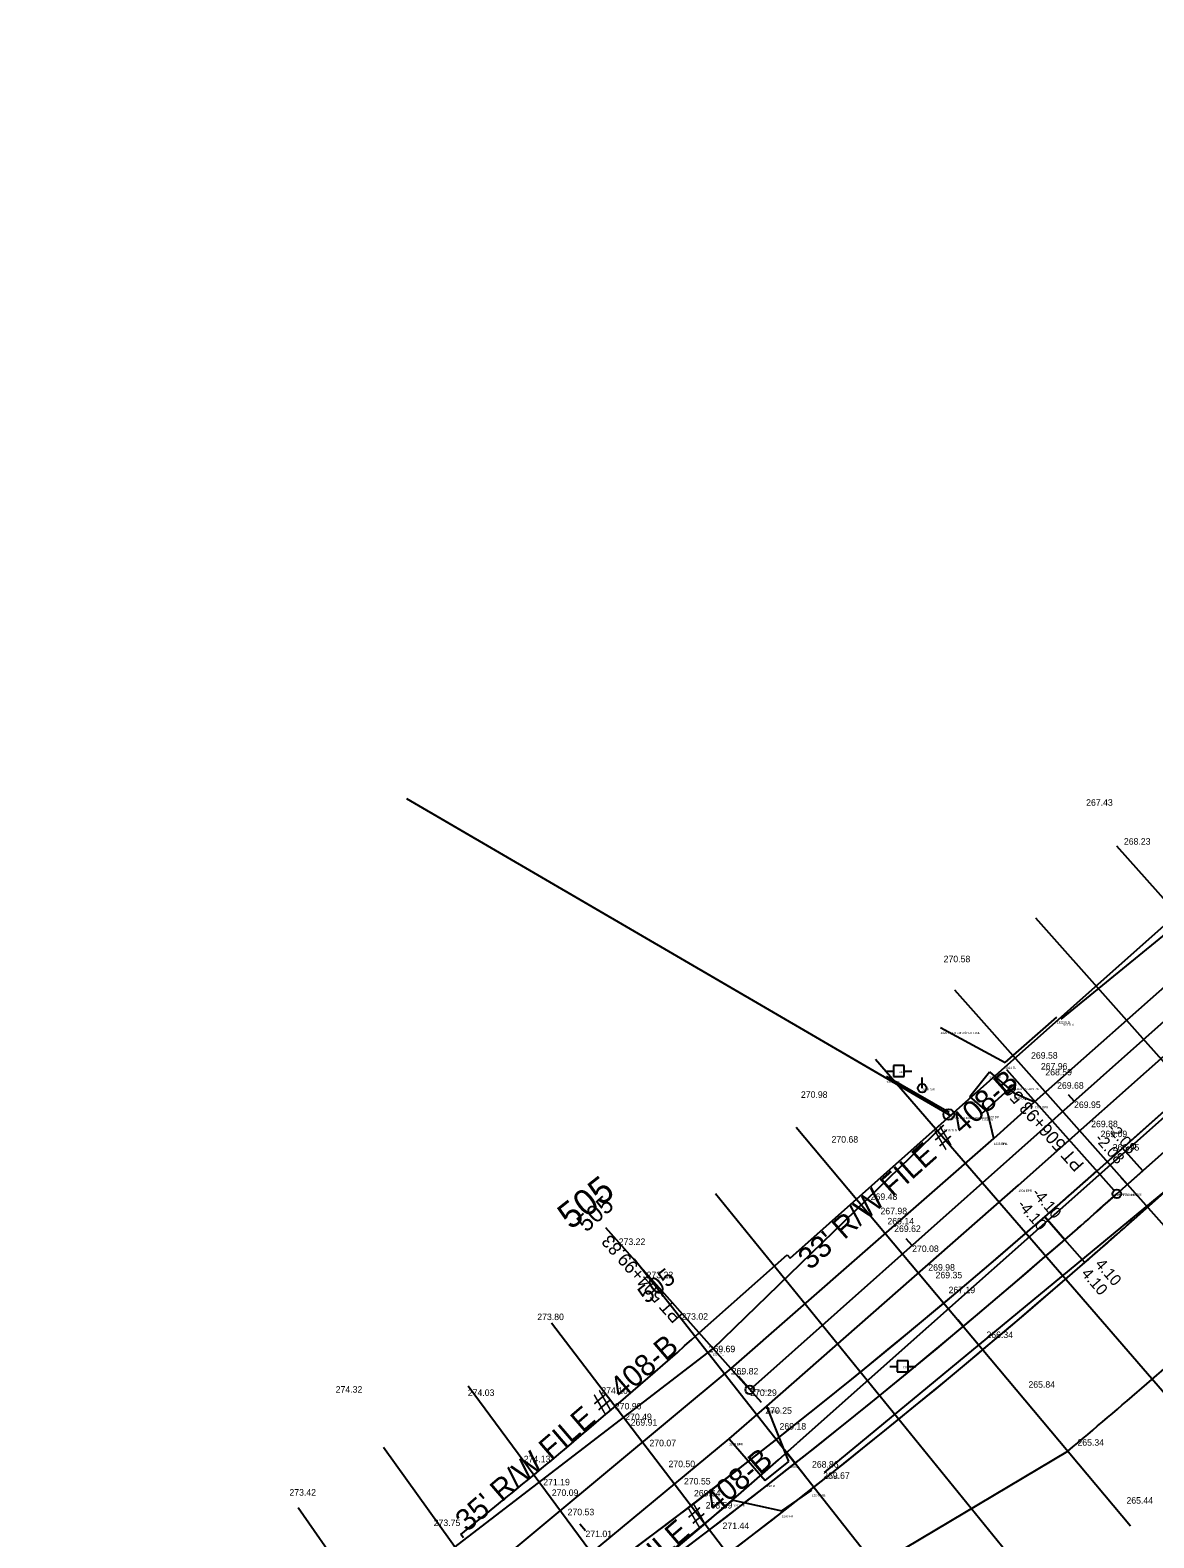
# Model space of a CAD drawing. Extents: x 49683 to 58852, y 49525 to 54803.
# Drawn here: x 52213 to 52731, y 50615 to 51310 of the extents above; entities that cross this region are included whole.
import ezdxf

# ---------------------------------------------------------------- set-up
doc = ezdxf.new("R2010")
doc.units = 0
for name, color, linetype in [('Level 1', 7, 'Continuous'), ('Level 11', 7, 'Continuous'), ('Level 12', 7, 'Continuous'), ('Level 13', 7, 'Continuous'), ('Level 19', 7, 'Continuous'), ('Level 20', 7, 'Continuous'), ('Level 21', 7, 'Continuous'), ('Level 25', 7, 'Continuous'), ('Level 29', 7, 'Continuous'), ('Level 3', 7, 'Continuous'), ('Level 32', 7, 'Continuous'), ('Level 33', 7, 'Continuous'), ('Level 50', 7, 'Continuous'), ('Level 51', 7, 'Continuous'), ('Level 53', 7, 'Continuous'), ('Level 56', 7, 'Continuous'), ('Level 58', 7, 'Continuous'), ('Level 59', 7, 'Continuous'), ('Level 6', 7, 'Continuous'), ('Level 61', 7, 'Continuous'), ('Level 62', 7, 'Continuous'), ('Level 63', 7, 'Continuous'), ('Level 8', 7, 'Continuous'), ('Level 9', 7, 'Continuous')]:
    doc.layers.add(name, color=color, linetype=linetype)

# ---------------------------------------------------------------- blocks, each defined once
blk = doc.blocks.new('PP')
at = {"layer": 'Level 9'}
for p, q in [((2.53, 2.45), (-2.47, 2.45)), ((-2.47, 2.45), (-2.47, -2.55)), ((2.53, -2.55), (2.53, 2.45)), ((-5.91, -0.11), (-2.44, -0.11)), ((-2.47, -2.55), (2.53, -2.55)), ((2.45, -0.11), (6.09, -0.11))]:
    blk.add_line(p, q, dxfattribs=at)
blk = doc.blocks.new('GW')
at = {"layer": 'Level 9'}
blk.add_line((0, 0), (0, 5), dxfattribs=at)
blk.add_circle((0, 0), 2, dxfattribs=at)
blk = doc.blocks.new('IP')
at = {"layer": 'Level 12'}
for radius in [2.5, 0.25]:
    blk.add_circle((0, 0), radius, dxfattribs=at)

msp = doc.modelspace()

# ---------------------------------------------------------------- linework, layer by layer
at = {"layer": 'Level 1'}
for p, q in [((52544.81, 50683.3), (55534.58, 53340.86)), ((52694.42, 50816.29), (52691.76, 50819.28)), ((52543.48, 50684.8), (52478.41, 50758)), ((52619.68, 50749.85), (52617.02, 50752.84)), ((52544.94, 50683.42), (52539.62, 50689.4)), ((52550.25, 50677.44), (52544.94, 50683.42)), ((52469.06, 50618.29), (52466.5, 50621.38))]:
    msp.add_line(p, q, dxfattribs=at)
msp.add_circle((52544.81, 50683.3), 2, dxfattribs=at)
at = {"layer": 'Level 11'}
for p, q in [((52688.43, 50854.08), (52940.3, 51059.99)), ((52579.25, 50645.17), (52882.73, 50895.61)), ((52527.71, 50702.05), (52634.35, 50805.36)), ((52331.92, 50551.79), (52527.71, 50702.05))]:
    msp.add_line(p, q, dxfattribs=at)
at = {"layer": 'Level 12'}
for p, q in [((52386.57, 50955.87), (52637.37, 50809.73)), ((52412.79, 50615.02), (52411.54, 50616.58))]:
    msp.add_line(p, q, dxfattribs=at)
at = {"layer": 'Level 13'}
for p, q in [((52637.37, 50809.73), (53363.85, 51455.49)), ((53407.7, 51406.16), (52566.74, 50658.64)), ((52563.41, 50743.99), (52637.37, 50809.73)), ((52521.55, 50709.46), (52562.08, 50745.49)), ((52562.08, 50745.49), (52563.41, 50743.99))]:
    msp.add_line(p, q, dxfattribs=at)
for radius, start, end in [(2829.79, 308.71775, 311.63328), (2897.79, 282.71776, 311.63339)]:
    msp.add_arc((50641.55, 52824.48), radius, start, end, dxfattribs=at)
at = {"layer": 'Level 19'}
for p, q in [((52714.15, 50773.62), (54181.77, 52078.16)), ((52712.83, 50775.12), (52663.38, 50830.74)), ((52718.97, 50777.9), (52716.31, 50780.89)), ((52643.35, 50712.47), (52640.78, 50715.54)), ((52565.77, 50649.38), (52560.82, 50655.66)), ((52565.77, 50649.38), (52570.72, 50643.1))]:
    msp.add_line(p, q, dxfattribs=at)
msp.add_circle((52714.15, 50773.62), 2, dxfattribs=at)
msp.add_arc((50539, 53220.69), 3274.06, 284.51284, 311.63337, dxfattribs=at)
at = {"layer": 'Level 20'}
for p, q in [((52704.85, 50784.08), (53476.26, 51469.77)), ((52723.45, 50763.15), (53495.78, 51449.66))]:
    msp.add_line(p, q, dxfattribs=at)
for radius in [3260.06, 3288.06]:
    msp.add_arc((50539, 53220.69), radius, 284.51284, 311.63318, dxfattribs=at)
at = {"layer": 'Level 29'}
for p, q in [((52714.15, 50773.62), (54181.77, 52078.16)), ((52712.83, 50775.12), (52663.38, 50830.74)), ((52718.97, 50777.9), (52716.31, 50780.89)), ((52643.35, 50712.47), (52640.78, 50715.54)), ((52565.77, 50649.38), (52560.82, 50655.66))]:
    msp.add_line(p, q, dxfattribs=at)
msp.add_circle((52714.15, 50773.62), 2, dxfattribs=at)
msp.add_arc((50539, 53220.69), 3274.06, 284.51246, 311.63337, dxfattribs=at)
at = {"layer": 'Level 3'}
for p, q in [((52676.2, 50815.96), (52945.93, 51055.32)), ((52668.7, 50777.53), (52961.4, 51037.52)), ((52657.35, 50799.14), (52676.2, 50815.96)), ((52536.19, 50693.05), (52657.35, 50799.14)), ((52552.71, 50675.77), (52668.7, 50777.53)), ((52383.07, 50565.65), (52536.19, 50693.05)), ((52535.34, 50660.73), (52552.71, 50675.77)), ((52398.28, 50547.35), (52535.34, 50660.73))]:
    msp.add_line(p, q, dxfattribs=at)
at = {"layer": 'Level 33'}
msp.add_line((52602.91, 50602.26), (52691.55, 50655.02), dxfattribs=at)
msp.add_arc((50539, 53220.69), 3349.06, 309.99611, 311.63318, dxfattribs=at)
at = {"layer": 'Level 50'}
for p, q in [((52713.99, 50934.03), (52873.43, 50754.65)), ((52676.62, 50900.81), (52836.06, 50721.43)), ((52639.25, 50867.59), (52798.69, 50688.21)), ((52602.88, 50835.64), (52759.93, 50654.16)), ((52566.22, 50804.4), (52720.48, 50620.54)), ((52529.09, 50773.73), (52680.52, 50587.53)), ((52491.49, 50743.62), (52640.06, 50555.14)), ((52453.43, 50714.1), (52599.11, 50523.36)), ((52414.93, 50685.15), (52557.67, 50492.22)), ((52375.99, 50656.8), (52515.77, 50461.71)), ((52336.62, 50629.05), (52473.41, 50431.84))]:
    msp.add_line(p, q, dxfattribs=at)
at = {"layer": 'Level 6'}
msp.add_line((52667.22, 50824.46), (52651.63, 50810.3), dxfattribs=at)
at = {"layer": 'Level 63'}
for p, q in [((52716.81, 50794.72), (53451.1, 51447.41)), ((53460.4, 51436.95), (52726.11, 50784.25)), ((52714.15, 50773.62), (52800.86, 50850.69)), ((52810.16, 50840.23), (52723.45, 50763.15)), ((52716.81, 50794.72), (52704.85, 50784.08)), ((52726.11, 50784.25), (52716.81, 50794.72)), ((52726.11, 50784.25), (52716.81, 50794.72)), ((52714.15, 50773.62), (52726.11, 50784.25)), ((52690.14, 50752.48), (52680.94, 50763.04)), ((52680.94, 50763.04), (52690.14, 50752.48)), ((52699.33, 50741.93), (52690.14, 50752.48)), ((52699.33, 50741.93), (52690.14, 50752.48))]:
    msp.add_line(p, q, dxfattribs=at)
for radius, start, end in [(3260.06, 311.07341, 311.63319), (3274.06, 311.07341, 311.63337), (3274.06, 311.07341, 311.63337), (3260.06, 284.51284, 311.07341), (3288.06, 311.07341, 311.63319), (3274.06, 284.51284, 311.07341), (3274.06, 284.51284, 311.07341), (3288.06, 284.51284, 311.07341)]:
    msp.add_arc((50539, 53220.69), radius, start, end, dxfattribs=at)
at = {"layer": 'Level 8'}
for p, q in [((52662.65, 50834.17), (52686.48, 50855.13)), ((52632.81, 50850.29), (52662.65, 50834.17)), ((52636.74, 50811.07), (52607.92, 50827.67)), ((52646.27, 50818.43), (52655.35, 50829.84)), ((52655.35, 50829.84), (52666.62, 50820.18)), ((52654.44, 50811.48), (52646.27, 50818.43)), ((52666.62, 50820.18), (52676.2, 50815.96)), ((52657.35, 50799.14), (52654.44, 50811.48)), ((52562.88, 50650.26), (52552.71, 50675.77)), ((52535.34, 50660.73), (52551.99, 50641.44)), ((52551.99, 50641.44), (52562.88, 50650.26)), ((52559.58, 50627.44), (52573.52, 50637.05)), ((52412.59, 50530.13), (52537.26, 50632.33)), ((52537.26, 50632.33), (52559.58, 50627.44))]:
    msp.add_line(p, q, dxfattribs=at)

# ---------------------------------------------------------------- block references
at = {"layer": 'Level 12'}
msp.add_blockref('IP', (52636.62, 50810.17), dxfattribs=at)
at = {"layer": 'Level 9'}
for name, p in [('PP', (52613.57, 50830.29)), ('GW', (52624.36, 50822.3)), ('PP', (52615.32, 50694.1))]:
    msp.add_blockref(name, p, dxfattribs=at)

# ---------------------------------------------------------------- texts
at = {"layer": 'Level 1'}
msp.add_text('PT 504+99.83', height=6, rotation=131.63333, dxfattribs=at).set_placement((52514.08, 50717.4))
at = {"layer": 'Level 19'}
for s, height, rotation, p in [('PT 506+93.56', 6, 131.63336, (52699.37, 50787.24)), ('505', 8, 38.24612, (52497.19, 50722.66))]:
    msp.add_text(s, height=height, rotation=rotation, dxfattribs=at).set_placement(p)
at = {"layer": 'Level 21'}
for height, rotation, p in [(12, 38.24612, (52462.28, 50756.75)), (8, 41.63333, (52469.43, 50755.59))]:
    msp.add_text('505', height=height, rotation=rotation, dxfattribs=at).set_placement(p)
at = {"layer": 'Level 25'}
for s, rotation, p in [("33' R/W FILE # 408-B", 41.63333, (52572.62, 50738.12)), ("35' R/W FILE # 408-B", 40.74622, (52414.47, 50617.41)), ("33' R/W FILE # 408-B", 40.72213, (52457.9, 50565.13))]:
    msp.add_text(s, height=10, rotation=rotation, dxfattribs=at).set_placement(p)
at = {"layer": 'Level 29'}
msp.add_text('PT 506+93.56', height=6, rotation=131.63336, dxfattribs=at).set_placement((52699.37, 50787.24))
at = {"layer": 'Level 32'}
for s, p in [('267.43', (52699.98, 50952.52)), ('268.23', (52717.38, 50934.57)), ('270.58', (52634.26, 50880.38)), ('269.58', (52674.56, 50835.92)), ('267.96', (52679.1, 50830.92)), ('268.59', (52681.16, 50828.21)), ('269.68', (52686.58, 50822.08)), ('270.98', (52568.44, 50817.86)), ('269.95', (52694.4, 50813.18)), ('269.88', (52702.29, 50804.34)), ('269.09', (52706.63, 50799.75)), ('270.68', (52582.55, 50797.22)), ('266.95', (52712.21, 50793.54)), ('269.48', (52600.61, 50770.8)), ('267.98', (52605.13, 50764.2)), ('269.14', (52608.33, 50759.52)), ('269.62', (52611.44, 50756.05)), ('273.22', (52484.4, 50750.05)), ('270.08', (52619.73, 50746.79)), ('269.98', (52627.18, 50738.19)), ('273.22', (52497.26, 50734.72)), ('269.35', (52630.53, 50734.64)), ('267.19', (52636.52, 50727.8)), ('273.80', (52446.85, 50715.4)), ('273.02', (52513.33, 50715.57)), ('266.34', (52653.99, 50707.13)), ('269.69', (52525.85, 50700.63)), ('269.69', (52525.9, 50700.58)), ('269.82', (52536.52, 50690.34)), ('274.32', (52353.88, 50681.95)), ('274.10', (52476.36, 50681.43)), ('265.84', (52673.36, 50684.23)), ('274.03', (52414.8, 50680.43)), ('270.29', (52545.04, 50680.43)), ('270.90', (52482.63, 50674.21)), ('270.49', (52487.39, 50669.32)), ('270.25', (52552.01, 50672.2)), ('269.91', (52489.93, 50666.75)), ('269.18', (52558.57, 50664.94)), ('270.07', (52498.57, 50657.24)), ('265.34', (52695.96, 50657.5)), ('274.13', (52440.6, 50649.87)), ('270.50', (52507.36, 50647.59)), ('268.86', (52573.54, 50647.39)), ('270.55', (52514.51, 50639.61)), ('269.67', (52578.68, 50642.22)), ('273.42', (52332.53, 50634.47)), ('271.19', (52449.59, 50639.21)), ('270.09', (52453.54, 50634.33)), ('269.64', (52519.11, 50634.11)), ('268.59', (52524.52, 50628.54)), ('265.44', (52718.56, 50630.78)), ('273.75', (52399.08, 50620.46)), ('270.53', (52460.84, 50625.42)), ('271.44', (52532.29, 50619.07)), ('271.01', (52469.07, 50615.34))]:
    msp.add_text(s, height=3, dxfattribs=at).set_placement(p)
at = {"layer": 'Level 51'}
for s, p in [('24 PT 506+93.55', (52714.15, 50772.62)), ('180 PT 506+93.55 ', (52714.15, 50772.62)), ('8 PT 504+99.83', (52544.81, 50682.3))]:
    msp.add_text(s, height=1, dxfattribs=at).set_placement(p)
at = {"layer": 'Level 53'}
for s, p in [('1312 EPL', (52676.2, 50812.96)), ('1305 EPL', (52657.35, 50796.14)), ('1304 EPR', (52668.7, 50774.53)), ('1295 EPL', (52536.19, 50690.05)), ('1300 EPR', (52552.71, 50672.77)), ('1296 EPR', (52535.34, 50657.73))]:
    msp.add_text(s, height=1, dxfattribs=at).set_placement(p)
at = {"layer": 'Level 56'}
for s, p in [('1313 PA 18IN RC', (52667.22, 50821.46)), ('1314 PB', (52651.63, 50807.3))]:
    msp.add_text(s, height=1, dxfattribs=at).set_placement(p)
at = {"layer": 'Level 58'}
for s, p in [('1322 FLB', (52686.48, 50852.13)), ('1320 FLA B 40IN SPLIT RAIL', (52632.81, 50847.29)), ('1321 FL', (52662.65, 50831.17)), ('1317 FLB', (52607.92, 50824.67)), ('1309 DP', (52655.35, 50826.84)), ('1308 DP', (52646.27, 50815.43)), ('1310 DP', (52666.62, 50817.18)), ('1307 DP', (52654.44, 50808.48)), ('1311 DPB', (52676.2, 50812.96)), ('1316 FLA B 40IN SPLIT RAIL', (52636.74, 50808.07)), ('1306 DPA', (52657.35, 50796.14)), ('1301 DB', (52552.71, 50672.77)), ('1297 DA', (52535.34, 50657.73)), ('1299 D', (52562.88, 50647.26)), ('1298 D', (52551.99, 50638.44)), ('1292 FR', (52537.26, 50629.33)), ('1294 FRB', (52573.52, 50634.05)), ('1293 FR', (52559.58, 50624.44))]:
    msp.add_text(s, height=1, dxfattribs=at).set_placement(p)
at = {"layer": 'Level 59'}
for s, p in [('1319 PP', (52613.57, 50829.29)), ('1318 GW', (52624.36, 50821.3)), ('1303 PP', (52615.32, 50693.1))]:
    msp.add_text(s, height=1, dxfattribs=at).set_placement(p)
at = {"layer": 'Level 61'}
for s, p in [('1323 TLA', (52688.43, 50851.08)), ('1315 TLB', (52634.35, 50802.36)), ('1291 TL', (52527.71, 50699.05)), ('1302 TRA', (52579.25, 50642.17))]:
    msp.add_text(s, height=1, dxfattribs=at).set_placement(p)
at = {"layer": 'Level 62'}
msp.add_text('1008 IP', height=1, dxfattribs=at).set_placement((52636.62, 50809.17))
at = {"layer": 'Level 63'}
for s, rotation, p in [('-2.08', 311.63346, (52709.38, 50803.49)), ('-2.08', 311.63346, (52703.61, 50798.8)), ('-4.10', 311.07357, (52674.6, 50773.75)), ('-4.10', 311.07357, (52667.88, 50768.33)), ('4.10', 311.07331, (52703.81, 50740.97)), ('4.10', 311.07331, (52697.44, 50736.65))]:
    msp.add_text(s, height=5.25, rotation=rotation, dxfattribs=at).set_placement(p)

doc.saveas('drawing.dxf')
